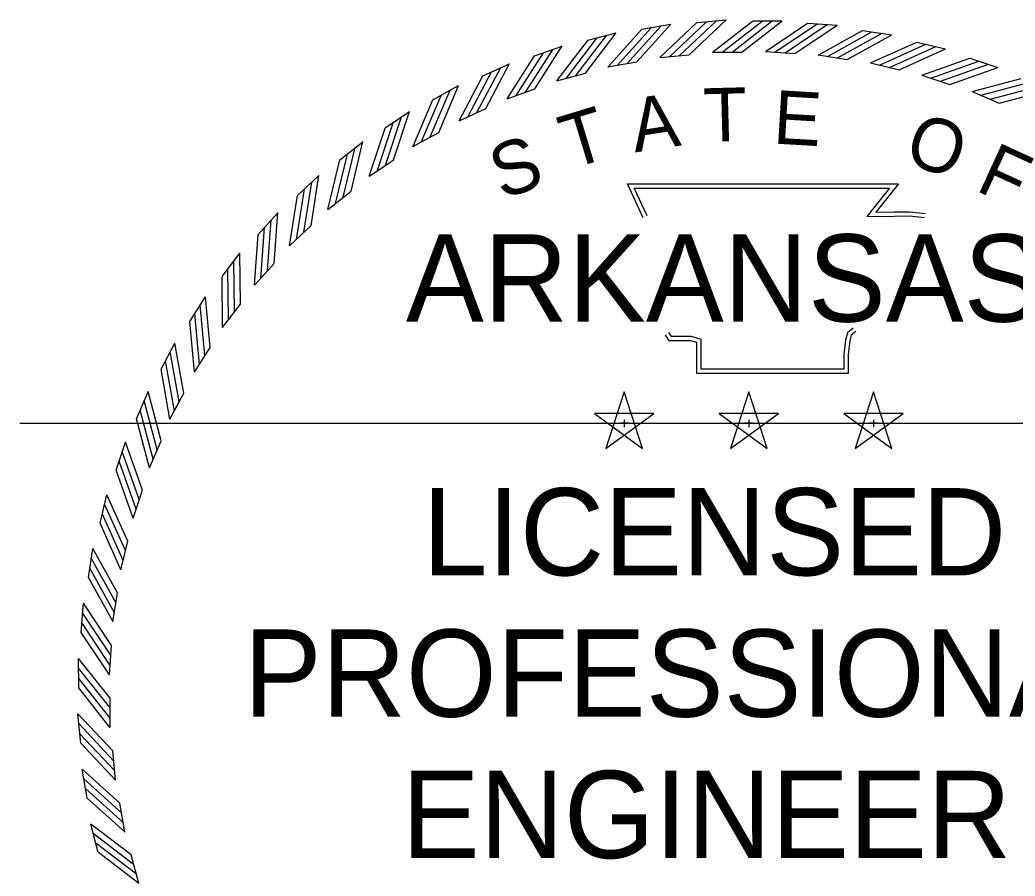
# Model space of a CAD drawing. Extents: x -712 to 3943, y 73 to 2823.
# Drawn here: x 2989.3 to 3144.5, y 278.8 to 412.2 of the extents above; entities that cross this region are included whole.
import ezdxf

# ---------------------------------------------------------------- set-up
doc = ezdxf.new("R2010")
doc.units = 0
doc.layers.add('SHET_Border-Lines', color=7, linetype='Continuous')
doc.layers.add('STAMP_TNC', color=7, linetype='Continuous')

msp = doc.modelspace()

# ---------------------------------------------------------------- linework, layer by layer
at = {"layer": 'SHET_Border-Lines'}
msp.add_lwpolyline([(2989.35, 349.36), (3223.63, 349.36)], dxfattribs=at)
msp.add_lwpolyline([(2989.35, 349.36), (3223.63, 349.36)], dxfattribs=at)
at = {"layer": 'STAMP_TNC'}
for p, q in [((3086.33, 410.78), (3090.85, 411.57)), ((3086.33, 410.78), (3090.85, 411.57)), ((3094.91, 411.8), (3099.47, 412.22)), ((3094.91, 411.8), (3099.47, 412.22)), ((3103.59, 412.06), (3108.17, 412.06)), ((3103.59, 412.06), (3108.17, 412.06)), ((3112.17, 411.71), (3116.74, 411.38)), ((3112.17, 411.71), (3116.74, 411.38)), ((3077.87, 409.05), (3082.3, 410.21)), ((3077.87, 409.05), (3082.3, 410.21)), ((3120.73, 410.6), (3125.26, 409.89)), ((3120.73, 410.6), (3125.26, 409.89)), ((3069.58, 406.62), (3073.9, 408.15)), ((3069.58, 406.62), (3073.9, 408.15)), ((3129.18, 408.78), (3133.63, 407.7)), ((3129.18, 408.78), (3133.63, 407.7)), ((3089.13, 406.37), (3093.7, 406.79)), ((3089.13, 406.37), (3093.7, 406.79)), ((3097.33, 407.18), (3101.93, 407.18)), ((3097.33, 407.18), (3101.93, 407.18)), ((3105.58, 407.31), (3110.16, 406.97)), ((3105.58, 407.31), (3110.16, 406.97)), ((3113.8, 406.76), (3118.34, 406.04)), ((3113.8, 406.76), (3118.34, 406.04)), ((3061.52, 403.53), (3065.7, 405.4)), ((3061.52, 403.53), (3065.7, 405.4)), ((3081.02, 404.89), (3085.55, 405.69)), ((3081.02, 404.89), (3085.55, 405.69)), ((3121.95, 405.53), (3126.41, 404.44)), ((3121.95, 405.53), (3126.41, 404.44)), ((3137.44, 406.28), (3141.79, 404.83)), ((3137.44, 406.28), (3141.79, 404.83)), ((3073.07, 402.74), (3077.51, 403.91)), ((3073.07, 402.74), (3077.51, 403.91)), ((3129.97, 403.63), (3134.33, 402.18)), ((3129.97, 403.63), (3134.33, 402.18)), ((3053.74, 399.77), (3057.75, 401.99)), ((3053.74, 399.77), (3057.75, 401.99)), ((3065.31, 399.94), (3069.64, 401.47)), ((3065.31, 399.94), (3069.64, 401.47)), ((3137.81, 401.07), (3142.03, 399.27)), ((3137.81, 401.07), (3142.03, 399.27)), ((3046.3, 395.39), (3050.11, 397.93)), ((3046.3, 395.39), (3050.11, 397.93)), ((3057.82, 396.51), (3062, 398.4)), ((3057.82, 396.51), (3062, 398.4)), ((3050.63, 392.48), (3054.65, 394.7)), ((3050.63, 392.48), (3054.65, 394.7)), ((3039.24, 390.41), (3042.83, 393.25)), ((3039.24, 390.41), (3042.83, 393.25)), ((3043.8, 387.86), (3047.62, 390.41)), ((3043.8, 387.86), (3047.62, 390.41)), ((3032.62, 384.86), (3035.97, 387.99)), ((3032.62, 384.86), (3035.97, 387.99)), ((3037.37, 382.7), (3040.97, 385.55)), ((3037.37, 382.7), (3040.97, 385.55)), ((3026.49, 378.78), (3029.56, 382.18)), ((3026.49, 378.78), (3029.56, 382.18)), ((3031.4, 377.02), (3034.75, 380.17)), ((3031.4, 377.02), (3034.75, 380.17)), ((3020.87, 372.22), (3023.65, 375.86)), ((3020.87, 372.22), (3023.65, 375.86)), ((3025.91, 370.87), (3028.99, 374.28)), ((3025.91, 370.87), (3028.99, 374.28)), ((3015.82, 365.22), (3018.29, 369.07)), ((3015.82, 365.22), (3018.29, 369.07)), ((3020.95, 364.29), (3023.74, 367.94)), ((3020.95, 364.29), (3023.74, 367.94)), ((3011.36, 357.82), (3013.5, 361.87)), ((3011.36, 357.82), (3013.5, 361.87)), ((3016.55, 357.32), (3019.03, 361.19)), ((3016.55, 357.32), (3019.03, 361.19)), ((3007.52, 350.08), (3009.33, 354.29)), ((3007.52, 350.08), (3009.33, 354.29)), ((3012.74, 350.01), (3014.89, 354.07)), ((3012.74, 350.01), (3014.89, 354.07)), ((3083.56, 354.24), (3080.7, 345.45)), ((3083.56, 354.24), (3080.7, 345.45)), ((3086.42, 345.45), (3083.57, 354.25)), ((3086.42, 345.45), (3083.57, 354.25)), ((3103, 354.24), (3100.13, 345.45)), ((3103, 354.24), (3100.13, 345.45)), ((3105.86, 345.45), (3103.01, 354.25)), ((3105.86, 345.45), (3103.01, 354.25)), ((3122.43, 354.24), (3119.57, 345.45)), ((3122.43, 354.24), (3119.57, 345.45)), ((3125.29, 345.45), (3122.44, 354.25)), ((3125.29, 345.45), (3122.44, 354.25)), ((3088.19, 350.89), (3078.94, 350.9)), ((3088.19, 350.89), (3078.94, 350.9)), ((3078.94, 350.89), (3086.42, 345.44)), ((3078.94, 350.89), (3086.42, 345.44)), ((3080.71, 345.45), (3088.2, 350.88)), ((3080.71, 345.45), (3088.2, 350.88)), ((3107.62, 350.89), (3098.37, 350.9)), ((3107.62, 350.89), (3098.37, 350.9)), ((3098.38, 350.89), (3105.86, 345.44)), ((3098.38, 350.89), (3105.86, 345.44)), ((3100.14, 345.45), (3107.63, 350.88)), ((3100.14, 345.45), (3107.63, 350.88)), ((3127.06, 350.89), (3117.81, 350.9)), ((3127.06, 350.89), (3117.81, 350.9)), ((3117.81, 350.89), (3125.29, 345.44)), ((3117.81, 350.89), (3125.29, 345.44)), ((3119.58, 345.45), (3127.07, 350.88)), ((3119.58, 345.45), (3127.07, 350.88)), ((3082.91, 349.41), (3084.28, 349.41)), ((3082.91, 349.41), (3084.28, 349.41)), ((3083.57, 349.9), (3083.57, 348.74)), ((3083.57, 349.9), (3083.57, 348.74)), ((3102.34, 349.41), (3103.72, 349.41)), ((3102.34, 349.41), (3103.72, 349.41)), ((3103.01, 349.9), (3103.01, 348.74)), ((3103.01, 349.9), (3103.01, 348.74)), ((3121.78, 349.41), (3123.15, 349.41)), ((3121.78, 349.41), (3123.15, 349.41)), ((3122.44, 349.9), (3122.44, 348.74)), ((3122.44, 349.9), (3122.44, 348.74)), ((3004.34, 342.05), (3005.79, 346.4)), ((3004.34, 342.05), (3005.79, 346.4)), ((3009.55, 342.41), (3011.35, 346.63)), ((3009.55, 342.41), (3011.35, 346.63)), ((3001.84, 333.78), (3002.92, 338.23)), ((3001.84, 333.78), (3002.92, 338.23)), ((3006.99, 334.58), (3008.44, 338.93)), ((3006.99, 334.58), (3008.44, 338.93)), ((3005.09, 326.55), (3006.18, 331.02)), ((3005.09, 326.55), (3006.18, 331.02)), ((3000.02, 325.34), (3000.73, 329.86)), ((3000.02, 325.34), (3000.73, 329.86)), ((3003.86, 318.4), (3004.58, 322.94)), ((3003.86, 318.4), (3004.58, 322.94)), ((2998.91, 316.77), (2999.24, 321.34)), ((2998.91, 316.77), (2999.24, 321.34)), ((3003.31, 310.18), (3003.65, 314.76)), ((3003.31, 310.18), (3003.65, 314.76)), ((2998.51, 308.15), (2998.47, 312.73)), ((2998.51, 308.15), (2998.47, 312.73)), ((3003.44, 301.94), (3003.4, 306.53)), ((3003.44, 301.94), (3003.4, 306.53)), ((2998.82, 299.51), (2998.4, 304.08)), ((2998.82, 299.51), (2998.4, 304.08)), ((3004.25, 293.74), (3003.83, 298.31)), ((3004.25, 293.74), (3003.83, 298.31)), ((2999.84, 290.94), (2999.05, 295.45)), ((2999.84, 290.94), (2999.05, 295.45)), ((3005.73, 285.63), (3004.93, 290.15)), ((3005.73, 285.63), (3004.93, 290.15)), ((3001.57, 282.48), (3000.41, 286.91)), ((3001.57, 282.48), (3000.41, 286.91)), ((3007.88, 277.67), (3006.71, 282.11)), ((3007.88, 277.67), (3006.71, 282.11))]:
    msp.add_line(p, q, dxfattribs=at)
for points in [[(3084.03, 405.44), (3089.34, 411.32)], [(3084.03, 405.44), (3089.34, 411.32)], [(3085.54, 405.69), (3090.85, 411.58)], [(3085.54, 405.69), (3090.85, 411.58)], [(3089.13, 406.37), (3094.9, 411.8)], [(3089.13, 406.37), (3094.9, 411.8)], [(3090.6, 406.49), (3096.37, 411.92)], [(3090.6, 406.49), (3096.37, 411.92)], [(3092.18, 406.67), (3097.96, 412.1)], [(3092.18, 406.67), (3097.96, 412.1)], [(3093.7, 406.8), (3099.48, 412.22)], [(3093.7, 406.8), (3099.48, 412.22)], [(3097.33, 407.18), (3103.58, 412.05)], [(3097.33, 407.18), (3103.58, 412.05)], [(3098.8, 407.16), (3105.05, 412.04)], [(3098.8, 407.16), (3105.05, 412.04)], [(3100.39, 407.2), (3106.65, 412.07)], [(3100.39, 407.2), (3106.65, 412.07)], [(3101.92, 407.18), (3108.17, 412.06)], [(3101.92, 407.18), (3108.17, 412.06)], [(3105.57, 407.3), (3112.16, 411.71)], [(3105.57, 407.3), (3112.16, 411.71)], [(3107.04, 407.18), (3113.63, 411.59)], [(3107.04, 407.18), (3113.63, 411.59)], [(3108.63, 407.1), (3115.22, 411.51)], [(3108.63, 407.1), (3115.22, 411.51)], [(3110.15, 406.98), (3116.74, 411.38)], [(3110.15, 406.98), (3116.74, 411.38)], [(3076.02, 403.54), (3080.83, 409.84)], [(3076.02, 403.54), (3080.83, 409.84)], [(3077.5, 403.91), (3082.31, 410.22)], [(3077.5, 403.91), (3082.31, 410.22)], [(3081.02, 404.88), (3086.33, 410.77)], [(3081.02, 404.88), (3086.33, 410.77)], [(3082.47, 405.13), (3087.78, 411.01)], [(3082.47, 405.13), (3087.78, 411.01)], [(3113.79, 406.75), (3120.73, 410.6)], [(3113.79, 406.75), (3120.73, 410.6)], [(3115.25, 406.51), (3122.18, 410.35)], [(3115.25, 406.51), (3122.18, 410.35)], [(3116.83, 406.3), (3123.76, 410.14)], [(3116.83, 406.3), (3123.76, 410.14)], [(3118.33, 406.05), (3125.27, 409.89)], [(3118.33, 406.05), (3125.27, 409.89)], [(3069.64, 401.48), (3073.9, 408.16)], [(3069.64, 401.48), (3073.9, 408.16)], [(3073.06, 402.74), (3077.87, 409.04)], [(3073.06, 402.74), (3077.87, 409.04)], [(3074.49, 403.1), (3079.3, 409.4)], [(3074.49, 403.1), (3079.3, 409.4)], [(3121.94, 405.52), (3129.17, 408.78)], [(3121.94, 405.52), (3129.17, 408.78)], [(3123.37, 405.16), (3130.6, 408.42)], [(3123.37, 405.16), (3130.6, 408.42)], [(3124.93, 404.82), (3132.16, 408.08)], [(3124.93, 404.82), (3132.16, 408.08)], [(3065.31, 399.94), (3069.58, 406.62)], [(3065.31, 399.94), (3069.58, 406.62)], [(3066.7, 400.42), (3070.97, 407.1)], [(3066.7, 400.42), (3070.97, 407.1)], [(3068.19, 400.98), (3072.46, 407.66)], [(3068.19, 400.98), (3072.46, 407.66)], [(3126.41, 404.44), (3133.64, 407.7)], [(3126.41, 404.44), (3133.64, 407.7)], [(3062, 398.4), (3065.7, 405.41)], [(3062, 398.4), (3065.7, 405.41)], [(3129.96, 403.63), (3137.44, 406.28)], [(3129.96, 403.63), (3137.44, 406.28)], [(3131.36, 403.15), (3138.83, 405.8)], [(3131.36, 403.15), (3138.83, 405.8)], [(3132.88, 402.68), (3140.35, 405.33)], [(3132.88, 402.68), (3140.35, 405.33)], [(3057.81, 396.51), (3061.51, 403.52)], [(3057.81, 396.51), (3061.51, 403.52)], [(3059.16, 397.1), (3062.87, 404.11)], [(3059.16, 397.1), (3062.87, 404.11)], [(3060.6, 397.79), (3064.3, 404.8)], [(3060.6, 397.79), (3064.3, 404.8)], [(3134.32, 402.18), (3141.8, 404.83)], [(3134.32, 402.18), (3141.8, 404.83)], [(3054.64, 394.7), (3057.75, 401.99)], [(3054.64, 394.7), (3057.75, 401.99)], [(3137.8, 401.07), (3145.47, 403.1)], [(3137.8, 401.07), (3145.47, 403.1)], [(3139.15, 400.48), (3146.82, 402.5)], [(3139.15, 400.48), (3146.82, 402.5)], [(3140.63, 399.89), (3148.29, 401.91)], [(3140.63, 399.89), (3148.29, 401.91)], [(3051.92, 393.17), (3055.03, 400.47)], [(3051.92, 393.17), (3055.03, 400.47)], [(3053.3, 393.98), (3056.41, 401.27)], [(3053.3, 393.98), (3056.41, 401.27)], [(3142.03, 399.27), (3149.69, 401.3)], [(3142.03, 399.27), (3149.69, 401.3)], [(3050.63, 392.47), (3053.74, 399.77)], [(3050.63, 392.47), (3053.74, 399.77)], [(3047.61, 390.41), (3050.11, 397.94)], [(3047.61, 390.41), (3050.11, 397.94)], [(3045.03, 388.66), (3047.53, 396.19)], [(3045.03, 388.66), (3047.53, 396.19)], [(3046.34, 389.58), (3048.83, 397.1)], [(3046.34, 389.58), (3048.83, 397.1)], [(3043.8, 387.86), (3046.3, 395.38)], [(3043.8, 387.86), (3046.3, 395.38)], [(3040.97, 385.55), (3042.83, 393.26)], [(3040.97, 385.55), (3042.83, 393.26)], [(3038.54, 383.6), (3040.4, 391.3)], [(3038.54, 383.6), (3040.4, 391.3)], [(3039.76, 384.62), (3041.63, 392.32)], [(3039.76, 384.62), (3041.63, 392.32)], [(3037.37, 382.69), (3039.24, 390.4)], [(3037.37, 382.69), (3039.24, 390.4)], [(3034.74, 380.16), (3035.97, 388)], [(3034.74, 380.16), (3035.97, 388)], [(3033.62, 379.13), (3034.84, 386.96)], [(3033.62, 379.13), (3034.84, 386.96)], [(3086.52, 381.39), (3084.07, 386.68), (3126.33, 386.7), (3122.8, 382.27), (3125.67, 382.3), (3128.07, 382.34), (3130.47, 382.07)], [(3086.52, 381.39), (3084.07, 386.68), (3126.33, 386.7), (3122.8, 382.27), (3125.67, 382.3), (3128.07, 382.34), (3130.47, 382.07)], [(3031.4, 377.02), (3032.62, 384.85)], [(3031.4, 377.02), (3032.62, 384.85)], [(3032.48, 378.02), (3033.71, 385.85)], [(3032.48, 378.02), (3033.71, 385.85)], [(3087.12, 381.67), (3085.12, 386.01), (3124.94, 386.03), (3121.4, 381.58), (3125.68, 381.64), (3128.04, 381.67), (3130.39, 381.41)], [(3087.12, 381.67), (3085.12, 386.01), (3124.94, 386.03), (3121.4, 381.58), (3125.68, 381.64), (3128.04, 381.67), (3130.39, 381.41)], [(3028.98, 374.28), (3029.56, 382.19)], [(3028.98, 374.28), (3029.56, 382.19)], [(3027.95, 373.16), (3028.52, 381.06)], [(3027.95, 373.16), (3028.52, 381.06)], [(3025.91, 370.87), (3026.48, 378.77)], [(3025.91, 370.87), (3026.48, 378.77)], [(3026.91, 371.95), (3027.48, 379.86)], [(3026.91, 371.95), (3027.48, 379.86)], [(3023.73, 367.94), (3023.65, 375.87)], [(3023.73, 367.94), (3023.65, 375.87)], [(3022.79, 366.73), (3022.71, 374.66)], [(3022.79, 366.73), (3022.71, 374.66)], [(3021.86, 365.45), (3021.78, 373.38)], [(3021.86, 365.45), (3021.78, 373.38)], [(3020.95, 364.28), (3020.87, 372.21)], [(3020.95, 364.28), (3020.87, 372.21)], [(3018.19, 359.91), (3017.45, 367.8)], [(3018.19, 359.91), (3017.45, 367.8)], [(3019.02, 361.19), (3018.29, 369.08)], [(3019.02, 361.19), (3018.29, 369.08)], [(3017.36, 358.55), (3016.62, 366.44)], [(3017.36, 358.55), (3016.62, 366.44)], [(3016.55, 357.31), (3015.82, 365.21)], [(3016.55, 357.31), (3015.82, 365.21)], [(3119.67, 363.68), (3118.95, 363.09), (3118.71, 362.22), (3118.47, 360.03), (3118.47, 357.11), (3094.88, 357.11), (3094.88, 361.05), (3094.88, 361.93), (3093.93, 362.22), (3090.57, 362.22), (3089.98, 363.13)], [(3119.67, 363.68), (3118.95, 363.09), (3118.71, 362.22), (3118.47, 360.03), (3118.47, 357.11), (3094.88, 357.11), (3094.88, 361.05), (3094.88, 361.93), (3093.93, 362.22), (3090.57, 362.22), (3089.98, 363.13)], [(3119.25, 364.2), (3118.36, 363.48), (3118.05, 362.34), (3117.8, 360.06), (3117.8, 357.78), (3095.55, 357.78), (3095.55, 361.05), (3095.55, 362.42), (3094.03, 362.89), (3090.93, 362.89), (3090.54, 363.49)], [(3119.25, 364.2), (3118.36, 363.48), (3118.05, 362.34), (3117.8, 360.06), (3117.8, 357.78), (3095.55, 357.78), (3095.55, 361.05), (3095.55, 362.42), (3094.03, 362.89), (3090.93, 362.89), (3090.54, 363.49)], [(3014.88, 354.07), (3013.5, 361.87)], [(3014.88, 354.07), (3013.5, 361.87)], [(3014.16, 352.72), (3012.77, 360.53)], [(3014.16, 352.72), (3012.77, 360.53)], [(3013.44, 351.3), (3012.06, 359.11)], [(3013.44, 351.3), (3012.06, 359.11)], [(3012.74, 350), (3011.36, 357.81)], [(3012.74, 350), (3011.36, 357.81)], [(3011.35, 346.63), (3009.32, 354.3)], [(3011.35, 346.63), (3009.32, 354.3)], [(3010.74, 345.23), (3008.71, 352.9)], [(3010.74, 345.23), (3008.71, 352.9)], [(3010.14, 343.76), (3008.12, 351.42)], [(3010.14, 343.76), (3008.12, 351.42)], [(3009.55, 342.41), (3007.52, 350.07)], [(3009.55, 342.41), (3007.52, 350.07)], [(3008.44, 338.93), (3005.79, 346.4)], [(3008.44, 338.93), (3005.79, 346.4)], [(3007.94, 337.48), (3005.29, 344.96)], [(3007.94, 337.48), (3005.29, 344.96)], [(3007.47, 335.96), (3004.82, 343.44)], [(3007.47, 335.96), (3004.82, 343.44)], [(3007, 334.57), (3004.34, 342.04)], [(3007, 334.57), (3004.34, 342.04)], [(3006.18, 331.01), (3002.92, 338.24)], [(3006.18, 331.01), (3002.92, 338.24)], [(3005.8, 329.53), (3002.54, 336.76)], [(3005.8, 329.53), (3002.54, 336.76)], [(3005.46, 327.98), (3002.2, 335.21)], [(3005.46, 327.98), (3002.2, 335.21)], [(3005.1, 326.55), (3001.84, 333.78)], [(3005.1, 326.55), (3001.84, 333.78)], [(3004.57, 322.94), (3000.73, 329.87)], [(3004.57, 322.94), (3000.73, 329.87)], [(3004.32, 321.43), (3000.48, 328.36)], [(3004.32, 321.43), (3000.48, 328.36)], [(3004.11, 319.85), (3000.27, 326.79)], [(3004.11, 319.85), (3000.27, 326.79)], [(3003.87, 318.4), (3000.02, 325.33)], [(3003.87, 318.4), (3000.02, 325.33)], [(3003.65, 314.75), (2999.24, 321.35)], [(3003.65, 314.75), (2999.24, 321.35)], [(3003.52, 313.23), (2999.12, 319.83)], [(3003.52, 313.23), (2999.12, 319.83)], [(3003.44, 311.64), (2999.03, 318.24)], [(3003.44, 311.64), (2999.03, 318.24)], [(3003.32, 310.17), (2998.91, 316.77)], [(3003.32, 310.17), (2998.91, 316.77)], [(3003.4, 306.53), (2998.46, 312.73)], [(3003.4, 306.53), (2998.46, 312.73)], [(3003.4, 305), (2998.46, 311.21)], [(3003.4, 305), (2998.46, 311.21)], [(3003.44, 303.41), (2998.51, 309.61)], [(3003.44, 303.41), (2998.51, 309.61)], [(3003.44, 301.93), (2998.51, 308.14)], [(3003.44, 301.93), (2998.51, 308.14)], [(3003.83, 298.3), (2998.4, 304.08)], [(3003.83, 298.3), (2998.4, 304.08)], [(3003.95, 296.78), (2998.52, 302.56)], [(3003.95, 296.78), (2998.52, 302.56)], [(3004.13, 295.2), (2998.7, 300.98)], [(3004.13, 295.2), (2998.7, 300.98)], [(3004.25, 293.73), (2998.83, 299.51)], [(3004.25, 293.73), (2998.83, 299.51)], [(3004.93, 290.14), (2999.05, 295.45)], [(3004.93, 290.14), (2999.05, 295.45)], [(3005.18, 288.64), (2999.3, 293.95)], [(3005.18, 288.64), (2999.3, 293.95)], [(3005.49, 287.08), (2999.61, 292.39)], [(3005.49, 287.08), (2999.61, 292.39)], [(3005.74, 285.62), (2999.85, 290.93)], [(3005.74, 285.62), (2999.85, 290.93)], [(3006.71, 282.1), (3000.4, 286.91)], [(3006.71, 282.1), (3000.4, 286.91)], [(3007.08, 280.63), (3000.78, 285.43)], [(3007.08, 280.63), (3000.78, 285.43)], [(3007.52, 279.09), (3001.22, 283.9)], [(3007.52, 279.09), (3001.22, 283.9)], [(3007.89, 277.67), (3001.58, 282.47)], [(3007.89, 277.67), (3001.58, 282.47)]]:
    msp.add_lwpolyline(points, dxfattribs=at)

# ---------------------------------------------------------------- texts
for s, rotation, p in [('A', 8.6788, (3085.23, 391.56)), ('A', 8.6788, (3085.23, 391.56)), ('T', 1.4789, (3095.99, 393.22)), ('T', 1.4789, (3095.99, 393.22)), ('E', 356.672, (3106.66, 392.97)), ('E', 356.672, (3106.66, 392.97)), ('T', 16.9015, (3075.11, 388.92)), ('T', 16.9015, (3075.11, 388.92)), ('O', 341.2218, (3126.9, 390.11)), ('O', 341.2218, (3126.9, 390.11)), ('S', 19.7726, (3064.51, 384.16)), ('S', 19.7726, (3064.51, 384.16)), ('F', 335.3628, (3138.13, 385.72)), ('F', 335.3628, (3138.13, 385.72))]:
    msp.add_text(s, height=8.34, rotation=rotation, dxfattribs=at).set_placement(p)
for s, height, p in [('ARKANSAS', 13.605, (3049.53, 365.2)), ('ARKANSAS', 13.605, (3049.53, 365.2)), ('LICENSED', 13.605, (3052.12, 325.66)), ('LICENSED', 13.605, (3052.12, 325.66)), ('PROFESSIONAL', 13.6047, (3024.26, 303.63)), ('PROFESSIONAL', 13.6047, (3024.26, 303.63)), ('ENGINEER', 13.605, (3048.88, 281.6)), ('ENGINEER', 13.605, (3048.88, 281.6))]:
    msp.add_text(s, height=height, dxfattribs=at).set_placement(p)

doc.saveas('drawing.dxf')
